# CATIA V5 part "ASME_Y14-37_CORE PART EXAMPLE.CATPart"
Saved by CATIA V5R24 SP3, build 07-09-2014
Part number: ASME Y14.37 - CORE EXAMPLE
Material "Honeycomb": density 40 kg/m3
Bounding box of the stored display mesh (mm): x -1012.309 to 1278.04, y -788.718 to 818.501, z 0 to 49.022
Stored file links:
  \\A5978449\c$\Users\jvl2147\Documents\ASME Y14.37\PartExamples\ASME_Y14-37_CORE PART EXAMPLE.CATPart
  C:\Users\jvl2147\Desktop\CompositesCatalog.CATMaterial
  \\Nw\787lib\787-PROCINT-WKG\Dom_SSDBS\DM\!!ShareFileForWritingServices\Composites\Standards and References\ASMEY-14.37\ASMEY-14.37_COMPOSITES.CATMaterial
  C:\Program Files\Dassault Systemes\B28SP5PRALL\win_b64\startup\materials\honeycomb.jpg
  \\Nw\787lib\787-PROCINT-WKG\Dom_SSDBS\DM\!!ShareFileForWritingServices\Composites\Standards and References\ASME Y14.37\PLY TABEL_-1 BOND ASSEMBLY.xlsx
  \\Nw\787lib\787-PROCINT-WKG\Dom_SSDBS\DM\!!ShareFileForWritingServices\Composites\Standards and References\ASME Y14.37\ASME_Y14.37_VALIDATION-PROPERTIES_CORE STIFFENED BOND PART.xlsx.xlsx
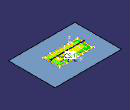
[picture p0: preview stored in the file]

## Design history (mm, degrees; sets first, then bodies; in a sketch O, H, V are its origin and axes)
Parameters
  StandardPlyThickness = 0.254 mm
  `Scale Value` = 100
CompParametersFeature1 "CATCoParametersFeatName": Value 0, Value 45, Value -45, Value 90, Orientations 999.999, Orientations 90
CompStacking1 "Stacking"
CompReviewTools1 "Review tools"
f4a2d38f3ddc11d3a929006094b99c4b_11 "CATTPSSet"
TTRSSet1
CompEOPGroupFeature1 "CATCoEOPGroupFeatName"
Toolside_View1 "CATTPSView"
Set1 "CONSTRUCTION (REF)"
  Sketch1 on XY plane of AxisSystem2, origin (0, 0, 0), H (1, 0, 0), V (0, 1, 0)
    line L1 (-1012.309, 818.5005) -> (1278.0398, 818.5005)
    line L2 (1278.0398, 818.5005) -> (1278.0398, -788.7181)
    line L3 (1278.0398, -788.7181) -> (-1012.309, -788.7181)
    line L4 (-1012.309, -788.7181) -> (-1012.309, 818.5005)
    horizontal: L1 H, L3 H
    vertical: L2 V, L4 V
  Fill1: Boundary Sketch1
  CurvePar1: Offset CompStdContourFeature1, Support Fill1, Offset2 0, Offset1 50.8
  Plane1: type Offset, RefPlane YZ plane of AxisSystem2, Offset -598
  Plane2: type Offset, RefPlane YZ plane of AxisSystem2, Offset -598, reversed
  Plane3: type Offset, RefPlane ZX plane of AxisSystem2, Offset -292
  Plane4: type Offset, RefPlane ZX plane of AxisSystem2, Offset -292, reversed
  MultiSel1
  CompStdContourFeature1 "CATCoStdContourFeatName": SupportSurface Fill1, ClosedSetOfCurves ({intersect ToIntersect1 Plane2, ToIntersect2 Fill1}; {intersect ToIntersect1 Plane3, ToIntersect2 Fill1}; {intersect ToIntersect1 Plane1, ToIntersect2 Fill1}; {intersect ToIntersect1 Plane4, ToIntersect2 Fill1}), ExtrapolDist 0.2
  Plane5: type Offset, RefPlane Plane2, Offset 254, reversed
  Intersect1: ToIntersect1 Plane5, ToIntersect2 Fill1
  Plane6: type Offset, RefPlane Plane1, Offset 254
  Intersect2: ToIntersect1 Plane6, ToIntersect2 Fill1
  Plane7: type Offset, RefPlane ZX plane of AxisSystem2, Offset -50.8
  CurvePar2: Offset CompStdContourFeature1, Offset2 0, Offset1 139.7
  Point1: (0, 0, 0), in AxisSystem2
  AxisSystem1: origin (0, 0, -127), X (1, 0, 0), Y (0, 1, 0), Z (0, 0, 1)
  Point2: (215.6851, 77.4411, 0)
  Point3: type OnCurve, Support edge [ZX plane of AxisSystem2 | YZ plane of AxisSystem2], Length 127
  Point4: type OnPlane, Support Join1, H -130.714, V 273.957, Direction (1, 0, 0)
  Split1: ToCut Circle1, Cutting {intersect ToIntersect1 Plane4, ToIntersect2 Fill1}
  Circle1: type CtrRad, Start 0, End 180, Center Point4, Support Join1, Radius 76.2, FirstDirection (1, 0, 0)
Set2 "ENGINEERING GEOMETRY"
  Join1 "TOOLSIDE SURFACE": Elements Fill1
  AxisSystem2 "PLY ORIENTATION COORDINATE SYSTEM": origin (0, 0, 0), X (1, 0, 0), Y (0, 1, 0), Z (0, 0, 1)
Set3 "EXPLODED PLIES VIEW (REF)"
  CLDGeom1 "PLY 1:10745:0"
  CLDGeom2 "PLY 2:10745:0"
  CLDGeom3 "PLY 3:10721:0"
  CLDGeom4 "PLY 4:10721:45"
  CLDGeom5 "PLY 5:10721:0"
  CLDGeom6 "PLY 6:10721:45"
  CLDGeom7 "PLY 7:10679:-45"
  DatumSurface1 "Core -103"
  CLDGeom8 "PLY 8:10679:0"
  CLDGeom9 "PLY 9:10721:0"
  CLDGeom10 "PLY 10:10721:-45"
  CLDGeom11 "PLY 11:10721:45"
  CLDGeom12 "PLY 12:10721:90"
Body1 "ASME_Y14.37_CORE_PART-101 (REF)" (main body)
  Solid1 "ASME_Y14.37_CORE_PART-101": solid without history
Body2 "CORE -103"
  CompCoreSolidFormGeometry1 "Geometry_8": Curves CurvePar1, ReferenceSurface Fill1, VariableOffsets 0, VariableSlopes 20, BasicHeight 25.4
